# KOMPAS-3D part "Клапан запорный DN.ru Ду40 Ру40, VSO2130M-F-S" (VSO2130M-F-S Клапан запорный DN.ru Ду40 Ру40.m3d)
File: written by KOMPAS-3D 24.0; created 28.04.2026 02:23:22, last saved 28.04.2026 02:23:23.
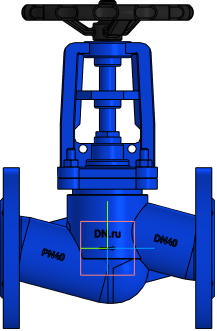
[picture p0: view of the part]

Document properties: Автор: DN.ru; Полное имя файла: C:\Работа\ГОТОВЫЕ ИСХОДНИКИ\VSO2130M-F-S Клапан запорный сильфонный DN.ru Ду15-100 Ру40\DN40\VSO2130M-F-S Клапан запорный DN.ru Ду40 Ру40.m3d

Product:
- Part/product: Клапан запорный DN.ru Ду40 Ру40  | designation VSO2130M-F-S
    Масса: 9
    Раздел спецификации: Прочие изделия
    Примечание: D090-01974

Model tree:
1. Операция без истории:1

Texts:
  VSO2130M-F-S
